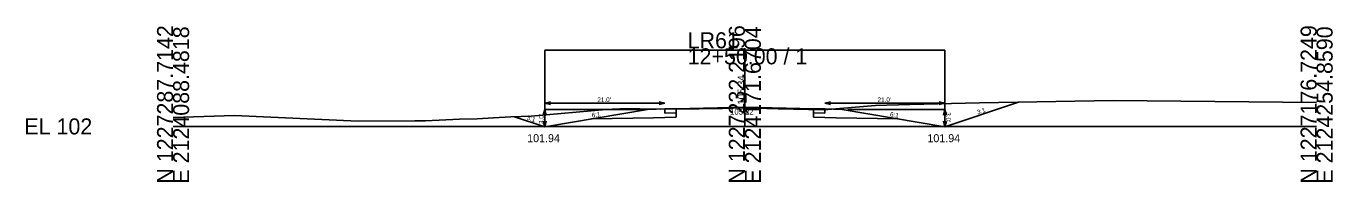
# Model space of a CAD drawing. Extents: x 2126751 to 2128979, y 1225108 to 1234639.
# Drawn here: x 2127750.9 to 2127979.4, y 1227607.5 to 1227634.7 of the extents above; entities that cross this region are included whole.
import ezdxf

# ---------------------------------------------------------------- set-up
doc = ezdxf.new("R2010")
doc.units = 0
for name, color, linetype in [('XS_CELL', 7, 'Continuous'), ('XS_M_DITCH', 7, 'Continuous'), ('XS_P_FINISHED_GRADE', 7, 'Continuous'), ('XS_P_FINISHED_GRADE_ELEV_TX', 7, 'Continuous'), ('XS_P_SUBGRADE_GRANULAR', 7, 'Continuous'), ('XS_P_SUBGRADE_LEVELING', 7, 'Continuous'), ('XS_P_SUBGRADE_PAVEMENT', 7, 'Continuous'), ('XS_P_TX_CLEARZONE', 7, 'Continuous'), ('XS_P_TX_DCH', 7, 'Continuous'), ('XS_P_TX_FS_BS', 7, 'Continuous'), ('XS_X_GROUND', 7, 'Continuous'), ('XS_X_GROUND_TX', 7, 'Continuous')]:
    doc.layers.add(name, color=color, linetype=linetype)

msp = doc.modelspace()

# ---------------------------------------------------------------- linework, layer by layer
at = {"layer": 'XS_CELL'}
for p, q in [((2127876.61, 1227617.21), (2127876.61, 1227630.86)), ((2127776.61, 1227617.21), (2127876.61, 1227617.21)), ((2127876.61, 1227617.21), (2127976.61, 1227617.21))]:
    msp.add_line(p, q, dxfattribs=at)
at = {"layer": 'XS_M_DITCH'}
for p, q in [((2127841.61, 1227617.15), (2127841.61, 1227630.55)), ((2127841.61, 1227630.55), (2127911.61, 1227630.55)), ((2127911.61, 1227630.55), (2127911.61, 1227617.15))]:
    msp.add_line(p, q, dxfattribs=at)
at = {"layer": 'XS_P_FINISHED_GRADE'}
for p, q in [((2127859.61, 1227620.15), (2127841.61, 1227617.15)), ((2127862.61, 1227620.27), (2127859.61, 1227620.15)), ((2127864.61, 1227620.31), (2127862.61, 1227620.27)), ((2127864.61, 1227620.31), (2127876.61, 1227620.55)), ((2127876.61, 1227620.55), (2127888.61, 1227620.31)), ((2127888.61, 1227620.31), (2127890.61, 1227620.27)), ((2127890.61, 1227620.27), (2127893.61, 1227620.15)), ((2127893.61, 1227620.15), (2127911.61, 1227617.15)), ((2127911.61, 1227617.15), (2127924.48, 1227621.44)), ((2127841.61, 1227617.15), (2127836.34, 1227618.91))]:
    msp.add_line(p, q, dxfattribs=at)
at = {"layer": 'XS_P_SUBGRADE_GRANULAR'}
for p, q in [((2127860.61, 1227618.73), (2127849.79, 1227618.52)), ((2127862.61, 1227618.77), (2127860.61, 1227618.73)), ((2127864.61, 1227618.81), (2127862.61, 1227618.77)), ((2127864.61, 1227618.81), (2127864.61, 1227619.56)), ((2127888.61, 1227618.81), (2127888.61, 1227619.56)), ((2127888.61, 1227618.81), (2127890.61, 1227618.77)), ((2127890.61, 1227618.77), (2127892.61, 1227618.73)), ((2127892.61, 1227618.73), (2127903.43, 1227618.52))]:
    msp.add_line(p, q, dxfattribs=at)
at = {"layer": 'XS_P_SUBGRADE_LEVELING'}
for p, q in [((2127864.61, 1227620.25), (2127872.69, 1227620.36)), ((2127864.61, 1227620.31), (2127864.61, 1227620.25)), ((2127872.69, 1227620.36), (2127876.41, 1227620.43)), ((2127876.41, 1227620.43), (2127882.44, 1227620.29)), ((2127882.44, 1227620.29), (2127888.61, 1227620.16)), ((2127888.61, 1227620.31), (2127888.61, 1227620.16))]:
    msp.add_line(p, q, dxfattribs=at)
at = {"layer": 'XS_P_SUBGRADE_PAVEMENT'}
for p, q in [((2127862.61, 1227619.52), (2127862.61, 1227620.27)), ((2127864.61, 1227619.56), (2127864.61, 1227620.25)), ((2127888.61, 1227619.56), (2127888.61, 1227620.16)), ((2127890.61, 1227619.52), (2127890.61, 1227620.27)), ((2127864.61, 1227619.56), (2127862.61, 1227619.52)), ((2127888.61, 1227619.56), (2127890.61, 1227619.52))]:
    msp.add_line(p, q, dxfattribs=at)
at = {"layer": 'XS_P_TX_CLEARZONE'}
for p, q in [((2127841.61, 1227620.15), (2127841.36, 1227619.15)), ((2127841.61, 1227621.27), (2127842.61, 1227621.52)), ((2127841.61, 1227621.27), (2127842.61, 1227621.02)), ((2127862.61, 1227621.27), (2127841.61, 1227621.27)), ((2127841.61, 1227620.15), (2127841.86, 1227619.15)), ((2127841.61, 1227620.15), (2127841.61, 1227617.15)), ((2127858.61, 1227620.15), (2127841.61, 1227620.15)), ((2127862.61, 1227621.27), (2127861.61, 1227621.52)), ((2127862.61, 1227621.27), (2127861.61, 1227621.02)), ((2127890.61, 1227621.27), (2127891.61, 1227621.52)), ((2127890.61, 1227621.27), (2127891.61, 1227621.02)), ((2127890.61, 1227621.27), (2127911.61, 1227621.27)), ((2127894.61, 1227620.15), (2127911.61, 1227620.15)), ((2127911.61, 1227621.27), (2127910.61, 1227621.52)), ((2127911.61, 1227621.27), (2127910.61, 1227621.02)), ((2127911.61, 1227620.15), (2127911.36, 1227619.15)), ((2127911.61, 1227620.15), (2127911.61, 1227617.15)), ((2127911.61, 1227620.15), (2127911.86, 1227619.15)), ((2127841.61, 1227617.15), (2127841.36, 1227618.15)), ((2127841.61, 1227617.15), (2127841.86, 1227618.15)), ((2127911.61, 1227617.15), (2127911.36, 1227618.15)), ((2127911.61, 1227617.15), (2127911.86, 1227618.15))]:
    msp.add_line(p, q, dxfattribs=at)
at = {"layer": 'XS_X_GROUND'}
for p, q in [((2127839.23, 1227618.98), (2127852.34, 1227620.16)), ((2127852.34, 1227620.16), (2127853.47, 1227620.21)), ((2127853.47, 1227620.21), (2127854.77, 1227620.26)), ((2127854.77, 1227620.26), (2127855.63, 1227620.28)), ((2127855.63, 1227620.28), (2127856.65, 1227620.3)), ((2127856.65, 1227620.3), (2127857.16, 1227620.31)), ((2127857.16, 1227620.31), (2127857.61, 1227620.31)), ((2127857.61, 1227620.31), (2127858.27, 1227620.31)), ((2127858.27, 1227620.31), (2127861.9, 1227620.21)), ((2127861.9, 1227620.21), (2127872.69, 1227620.36)), ((2127872.69, 1227620.36), (2127876.41, 1227620.43)), ((2127876.41, 1227620.43), (2127882.44, 1227620.29)), ((2127882.44, 1227620.29), (2127890.42, 1227620.13)), ((2127890.42, 1227620.13), (2127899.46, 1227620.88)), ((2127899.46, 1227620.88), (2127905.48, 1227621.04)), ((2127905.48, 1227621.04), (2127917.65, 1227621.31)), ((2127917.65, 1227621.31), (2127941, 1227621.76)), ((2127941, 1227621.76), (2127976.61, 1227621.38)), ((2127776.61, 1227618.75), (2127787.38, 1227619.12)), ((2127787.38, 1227619.12), (2127808.97, 1227618.13)), ((2127808.97, 1227618.13), (2127818.9, 1227618.17)), ((2127818.9, 1227618.17), (2127819.48, 1227618.18)), ((2127819.48, 1227618.18), (2127820.75, 1227618.21)), ((2127820.75, 1227618.21), (2127826.69, 1227618.47)), ((2127826.69, 1227618.47), (2127829.82, 1227618.51)), ((2127829.82, 1227618.51), (2127832.68, 1227618.7)), ((2127832.68, 1227618.7), (2127835.68, 1227618.89)), ((2127835.68, 1227618.89), (2127839.23, 1227618.98))]:
    msp.add_line(p, q, dxfattribs=at)

# ---------------------------------------------------------------- texts
at = {"layer": 'XS_CELL'}
for s, p in [('N 1227287.7142', (2127776.61, 1227607.21)), ('E 2124088.4818', (2127779.41, 1227607.21)), ('N 1227232.2196', (2127876.61, 1227607.21)), ('E 2124171.6704', (2127879.41, 1227607.21)), ('N 1227176.7249', (2127976.61, 1227607.21)), ('E 2124254.8590', (2127979.41, 1227607.21))]:
    msp.add_text(s, height=2.8, rotation=90, dxfattribs=at).set_placement(p)
for s, p in [('LR61', (2127866.61, 1227630.86)), ('12+50.00 / 1', (2127866.61, 1227628.06)), ('EL 102', (2127750.61, 1227615.81))]:
    msp.add_text(s, height=2.8, dxfattribs=at).set_placement(p)
at = {"layer": 'XS_P_FINISHED_GRADE_ELEV_TX'}
msp.add_text(' 105.34', height=1.25, rotation=90, dxfattribs=at).set_placement((2127876.61, 1227620.55))
at = {"layer": 'XS_P_TX_CLEARZONE'}
for p in [(2127850.82, 1227621.47), (2127899.82, 1227621.47)]:
    msp.add_text("21.0'", height=0.8, dxfattribs=at).set_placement(p)
for rotation, p in [(90, (2127841.41, 1227617.63)), (270, (2127911.81, 1227619.68))]:
    msp.add_text("3.0'", height=0.8, rotation=rotation, dxfattribs=at).set_placement(p)
at = {"layer": 'XS_P_TX_DCH'}
for p in [(2127838.54, 1227614.45), (2127908.54, 1227614.45)]:
    msp.add_text('101.94', height=1.4, dxfattribs=at).set_placement(p)
at = {"layer": 'XS_P_TX_FS_BS'}
for s, rotation, p in [('3:1', 18.4349, (2127917.33, 1227619.27)), ('3:1', 341.5651, (2127838.39, 1227618.44)), ('6:1', 9.4623, (2127849.89, 1227618.74)), ('6:1', 350.5377, (2127901.95, 1227618.97))]:
    msp.add_text(s, height=0.8, rotation=rotation, dxfattribs=at).set_placement(p)
at = {"layer": 'XS_X_GROUND_TX'}
msp.add_text('105.22', height=1, dxfattribs=at).set_placement((2127874.05, 1227619.27))

doc.saveas('drawing.dxf')
